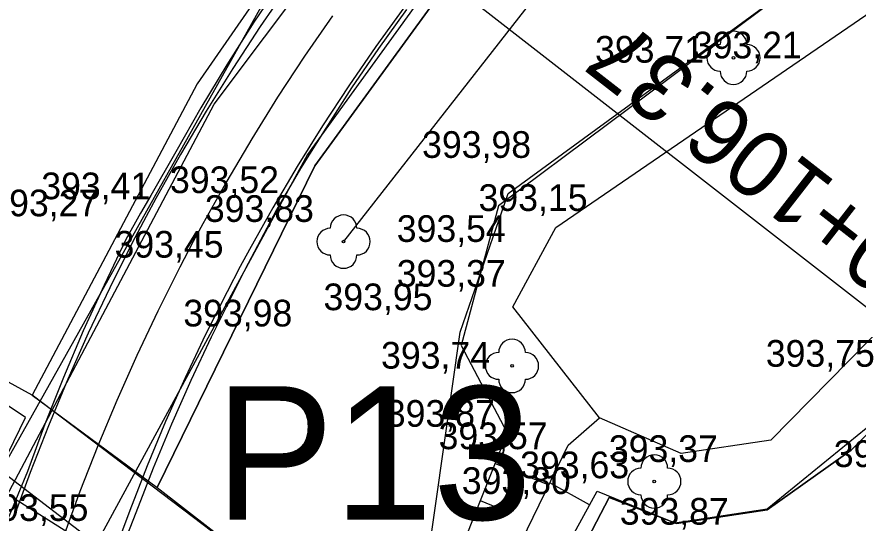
# Model space of a CAD drawing. Extents: x -574342 to -507939, y -1144044 to -1123894.
# Drawn here: x -508540.43 to -508508.86, y -1143172.06 to -1143153.08 of the extents above; entities that cross this region are included whole.
import ezdxf

# ---------------------------------------------------------------- set-up
doc = ezdxf.new("R2010")
doc.units = 0
for name, color, linetype in [('01_PARCELY_NAVRH_PC', 7, 'Continuous'), ('01_PARCELY_NAVRH_VHO', 7, 'Continuous'), ('01_PARCELY_NAVRH_ŽP', 7, 'Continuous'), ('03_PC_OBJEKTY_POP_NAVRH', 7, 'Continuous'), ('05_VHO_V_TOK_STAV', 7, 'Continuous'), ('1000', 7, 'Continuous'), ('18', 7, 'Continuous'), ('21', 7, 'Continuous'), ('23', 7, 'Continuous'), ('37', 7, 'Continuous'), ('42', 7, 'Continuous'), ('51', 7, 'Continuous'), ('54', 7, 'Continuous'), ('55', 7, 'Continuous'), ('60', 7, 'Continuous'), ('61', 7, 'Continuous'), ('Level 255', 7, 'Continuous'), ('Level24', 7, 'Continuous')]:
    doc.layers.add(name, color=color, linetype=linetype)

msp = doc.modelspace()

# ---------------------------------------------------------------- linework, layer by layer
at = {"layer": '01_PARCELY_NAVRH_PC'}
msp.add_lwpolyline([(-508539.86, -1143167.27), (-508535.17, -1143170.73), (-508529.25, -1143158.67), (-508513.07, -1143136.47), (-508505.79, -1143121.37), (-508501.93, -1143102.81), (-508501.63, -1143092.13), (-508497.53, -1143088.05), (-508492.06, -1143088.51), (-508489.36, -1143093.44), (-508498.08, -1143065.7), (-508506.03, -1143042.25), (-508507.09, -1143063.68), (-508507.1, -1143101.54), (-508510.16, -1143116.01), (-508515.95, -1143130.65), (-508519.02, -1143135.54), (-508530.41, -1143150.9), (-508533.66, -1143155.6)], close=True, dxfattribs=at)
msp.add_lwpolyline([(-508539.86, -1143167.27), (-508535.17, -1143170.73), (-508529.25, -1143158.67), (-508513.07, -1143136.47), (-508505.79, -1143121.37), (-508501.93, -1143102.81), (-508501.63, -1143092.13), (-508497.53, -1143088.05), (-508492.06, -1143088.51), (-508489.36, -1143093.44), (-508498.08, -1143065.7), (-508506.03, -1143042.25), (-508507.09, -1143063.68), (-508507.1, -1143101.54), (-508510.16, -1143116.01), (-508515.95, -1143130.65), (-508519.02, -1143135.54), (-508530.41, -1143150.9), (-508533.66, -1143155.6)], close=True, dxfattribs=at)
at = {"layer": '01_PARCELY_NAVRH_VHO'}
for points in [[(-508487.01, -1143113.01), (-508483.82, -1143117.57), (-508479.46, -1143126.74), (-508476.26, -1143134.7), (-508479.68, -1143136.88), (-508479.12, -1143143.52), (-508481.34, -1143149.03), (-508486.83, -1143153.3), (-508497.89, -1143158.09), (-508509.12, -1143169.33), (-508512.27, -1143171.56), (-508515.68, -1143172.08), (-508518.2, -1143171.1), (-508521.06, -1143176.58), (-508513.26, -1143177.6), (-508509.38, -1143179.27), (-508507.52, -1143173.92), (-508499.36, -1143164.43), (-508491.25, -1143159.19), (-508480.5, -1143156.13), (-508471.45, -1143157.79), (-508463.3, -1143163.03)], [(-508461.87, -1143244.49), (-508467.98, -1143243.62), (-508478.66, -1143222.38), (-508487.9, -1143213.8), (-508496.38, -1143198.1), (-508504.26, -1143191.1), (-508516.39, -1143188), (-508530.07, -1143174.68), (-508525.32, -1143175.64), (-508523.79, -1143164.91), (-508521.99, -1143159.7), (-508510.09, -1143151.01), (-508503.75, -1143144.67), (-508499.11, -1143135.6), (-508498.41, -1143129.24), (-508498.01, -1143119.91), (-508496.68, -1143115.27)], [(-508461.81, -1143244.49), (-508467.98, -1143243.62), (-508478.66, -1143222.38), (-508487.9, -1143213.8), (-508496.38, -1143198.1), (-508504.26, -1143191.1), (-508516.39, -1143188), (-508530.07, -1143174.68), (-508539.86, -1143167.27), (-508547.02, -1143163.34), (-508553.27, -1143164.53), (-508559.77, -1143166.35), (-508565.39, -1143163.91), (-508571.39, -1143166.22), (-508578.23, -1143159.53)]]:
    msp.add_lwpolyline(points, dxfattribs=at)
at = {"layer": '01_PARCELY_NAVRH_ŽP'}
for points in [[(-508523.79, -1143164.91), (-508521.99, -1143159.7), (-508510.09, -1143151.01), (-508503.75, -1143144.67), (-508499.11, -1143135.6), (-508498.41, -1143129.24), (-508498.01, -1143119.91), (-508496.68, -1143115.27), (-508492.61, -1143111.73), (-508487.01, -1143113.01), (-508489.36, -1143093.44), (-508492.06, -1143088.51), (-508497.53, -1143088.05), (-508501.63, -1143092.13), (-508501.93, -1143102.81), (-508505.79, -1143121.37), (-508513.07, -1143136.47), (-508529.25, -1143158.67), (-508535.17, -1143170.73), (-508530.07, -1143174.68), (-508525.32, -1143175.64)], [(-508521.06, -1143176.58), (-508518.2, -1143171.1), (-508515.68, -1143172.08), (-508512.27, -1143171.56), (-508509.12, -1143169.33), (-508497.89, -1143158.09), (-508486.83, -1143153.3), (-508481.34, -1143149.03), (-508479.12, -1143143.52), (-508479.68, -1143136.88), (-508476.26, -1143134.7), (-508463.3, -1143163.03), (-508471.45, -1143157.79), (-508480.5, -1143156.13), (-508491.25, -1143159.19), (-508499.36, -1143164.43), (-508507.52, -1143173.92), (-508509.38, -1143179.27), (-508513.26, -1143177.6)]]:
    msp.add_lwpolyline(points, close=True, dxfattribs=at)
msp.add_lwpolyline([(-508584.79, -1143151.71), (-508539.57, -1143146.61), (-508530.41, -1143150.9), (-508533.66, -1143155.6), (-508539.86, -1143167.27), (-508547.02, -1143163.34), (-508553.27, -1143164.53), (-508559.77, -1143166.35), (-508565.39, -1143163.91), (-508571.39, -1143166.22), (-508578.23, -1143159.53)], dxfattribs=at)
at = {"layer": '05_VHO_V_TOK_STAV'}
msp.add_lwpolyline([(-508453.89, -1143245.84), (-508469.84, -1143247.46), (-508476.067, -1143236.175), (-508482.77, -1143224.26), (-508489.11, -1143218.88), (-508496.94, -1143217.04), (-508494.75, -1143210.95), (-508502.24, -1143200.02), (-508504.69, -1143198.72), (-508508.04, -1143199.26), (-508513.72, -1143198.12), (-508516.16, -1143196.14), (-508515.31, -1143194.32), (-508517.287, -1143192.866), (-508519.733, -1143191.098), (-508522.24, -1143189.31), (-508524.27, -1143185.62), (-508530.674, -1143178.031), (-508542.01, -1143169.37), (-508547.92, -1143166.82), (-508560.33, -1143168.91), (-508565.27, -1143165.89), (-508572.15, -1143167.86), (-508577.98, -1143162.03)], dxfattribs=at)
at = {"layer": '1000'}
for points in [[(-508530.477, -1143151.708), (-508531.533, -1143153.28), (-508532.551, -1143154.877), (-508533.529, -1143156.497), (-508534.469, -1143158.14), (-508535.405, -1143159.783), (-508535.797, -1143160.446), (-508536.338, -1143161.431), (-508537.161, -1143163.136), (-508537.942, -1143164.859), (-508538.681, -1143166.6), (-508539.378, -1143168.358), (-508540.035, -1143170.13), (-508540.756, -1143171.879)], [(-508530.225, -1143151.886), (-508531.296, -1143153.44), (-508532.33, -1143155.018), (-508533.328, -1143156.619), (-508534.289, -1143158.243), (-508535.213, -1143159.888), (-508535.577, -1143160.563), (-508536.098, -1143161.555), (-508536.944, -1143163.241), (-508537.752, -1143164.947), (-508538.52, -1143166.67), (-508539.248, -1143168.411), (-508539.936, -1143170.168), (-508540.583, -1143171.94)], [(-508525.906, -1143152.739), (-508526.958, -1143154.193), (-508527.976, -1143155.671), (-508528.96, -1143157.172), (-508529.91, -1143158.695), (-508530.824, -1143160.24), (-508531.702, -1143161.805), (-508532.048, -1143162.447), (-508532.544, -1143163.391), (-508533.349, -1143164.995), (-508534.117, -1143166.617), (-508534.848, -1143168.256), (-508535.54, -1143169.912), (-508536.195, -1143171.583), (-508536.811, -1143173.269)], [(-508525.806, -1143152.813), (-508526.855, -1143154.266), (-508527.871, -1143155.742), (-508528.834, -1143157.253), (-508529.785, -1143158.771), (-508530.692, -1143160.316), (-508531.529, -1143161.9), (-508531.861, -1143162.547), (-508532.342, -1143163.495), (-508533.142, -1143165.095), (-508533.905, -1143166.714), (-508534.63, -1143168.35), (-508535.316, -1143170.003), (-508535.963, -1143171.671), (-508536.612, -1143173.339)]]:
    msp.add_lwpolyline(points, dxfattribs=at)
at = {"layer": '21'}
msp.add_lwpolyline([(-508528.592, -1143153.04), (-508529.636, -1143154.555), (-508530.645, -1143156.095), (-508531.619, -1143157.657), (-508532.556, -1143159.242), (-508533.457, -1143160.847), (-508533.813, -1143161.505), (-508534.321, -1143162.473), (-508535.147, -1143164.118), (-508535.934, -1143165.782), (-508536.684, -1143167.463), (-508537.394, -1143169.161), (-508538.065, -1143170.875), (-508538.697, -1143172.605)], dxfattribs=at)
at = {"layer": '23'}
msp.add_lwpolyline([(-508526.399, -1143150.082), (-508505.084, -1143166.654)], dxfattribs=at)
at = {"layer": '37'}
for points in [[(-508544.44, -1143182.59), (-508541.04, -1143171.49), (-508533.03, -1143156.36), (-508515.99, -1143133.69), (-508511.59, -1143124.92)], [(-508544.44, -1143182.59), (-508541.04, -1143171.49), (-508533.03, -1143156.36), (-508515.99, -1143133.69), (-508511.59, -1143124.92)], [(-508508.39, -1143126.78), (-508512.62, -1143134.91), (-508529.52, -1143158.24), (-508537.33, -1143172.61), (-508540.68, -1143183.59)], [(-508508.39, -1143126.78), (-508512.62, -1143134.91), (-508529.52, -1143158.24), (-508537.33, -1143172.61), (-508540.68, -1143183.59)]]:
    msp.add_lwpolyline(points, dxfattribs=at)
at = {"layer": '42'}
msp.add_lwpolyline([(-508584.52, -1143185.46), (-508576.94, -1143184.13), (-508565.72, -1143180.04), (-508541.6, -1143171.1), (-508528.13, -1143147.12), (-508515.55, -1143126.37), (-508515.49, -1143110.99), (-508517.48, -1143108.63), (-508537.36, -1143120.57)], dxfattribs=at)
msp.add_lwpolyline([(-508584.52, -1143185.46), (-508576.94, -1143184.13), (-508565.72, -1143180.04), (-508541.6, -1143171.1), (-508528.13, -1143147.12), (-508515.55, -1143126.37), (-508515.49, -1143110.99), (-508517.48, -1143108.63), (-508537.36, -1143120.57)], dxfattribs=at)
at = {"layer": '51'}
msp.add_lwpolyline([(-508520.2, -1143160.98), (-508507.66, -1143152.38), (-508503.68, -1143148.5), (-508498.94, -1143141.93), (-508496.26, -1143135.35), (-508495.95, -1143129.08), (-508495.44, -1143120.19), (-508493.12, -1143115.06), (-508490.39, -1143115.19), (-508486.94, -1143118.54), (-508484.73, -1143123.98), (-508484.03, -1143128.35), (-508482.47, -1143135.96), (-508481.24, -1143143.89), (-508483.67, -1143147.96), (-508487.25, -1143151.23), (-508497.6, -1143155.8), (-508504.12, -1143160.81), (-508512.14, -1143168.95), (-508515.5, -1143169.45), (-508518.57, -1143168.12), (-508521.82, -1143163.95)], close=True, dxfattribs=at)
msp.add_lwpolyline([(-508520.2, -1143160.98), (-508507.66, -1143152.38), (-508503.68, -1143148.5), (-508498.94, -1143141.93), (-508496.26, -1143135.35), (-508495.95, -1143129.08), (-508495.44, -1143120.19), (-508493.12, -1143115.06), (-508490.39, -1143115.19), (-508486.94, -1143118.54), (-508484.73, -1143123.98), (-508484.03, -1143128.35), (-508482.47, -1143135.96), (-508481.24, -1143143.89), (-508483.67, -1143147.96), (-508487.25, -1143151.23), (-508497.6, -1143155.8), (-508504.12, -1143160.81), (-508512.14, -1143168.95), (-508515.5, -1143169.45), (-508518.57, -1143168.12), (-508521.82, -1143163.95)], close=True, dxfattribs=at)
at = {"layer": '54'}
for centre in [(-508513.54, -1143154.62), (-508528.17, -1143161.51), (-508521.85, -1143166.17), (-508516.51, -1143170.5)]:
    msp.add_circle(centre, 0.05, dxfattribs=at)
for centre, start, end in [((-508513.54, -1143154.12), 0, 180), ((-508514.04, -1143154.62), 90, 270), ((-508513.04, -1143154.62), 270, 90), ((-508513.54, -1143155.12), 180, 0), ((-508528.17, -1143161.01), 0, 180), ((-508528.67, -1143161.51), 90, 270), ((-508527.67, -1143161.51), 270, 90), ((-508528.17, -1143162.01), 180, 0), ((-508521.85, -1143165.67), 0, 180), ((-508522.35, -1143166.17), 90, 270), ((-508521.35, -1143166.17), 270, 90), ((-508521.85, -1143166.67), 180, 0), ((-508516.51, -1143170), 0, 180), ((-508517.01, -1143170.5), 90, 270), ((-508516.01, -1143170.5), 270, 90), ((-508516.51, -1143171), 180, 0)]:
    msp.add_arc(centre, 0.5, start, end, dxfattribs=at)
at = {"layer": '55'}
msp.add_lwpolyline([(-508498.88, -1143086.48), (-508499.14, -1143104.9), (-508504.08, -1143125.77), (-508509.69, -1143137.89), (-508528.17, -1143161.51)], dxfattribs=at)
msp.add_lwpolyline([(-508498.88, -1143086.48), (-508499.14, -1143104.9), (-508504.08, -1143125.77), (-508509.69, -1143137.89), (-508528.17, -1143161.51)], dxfattribs=at)
at = {"layer": '60'}
for points in [[(-508515.74, -1143172.05), (-508512.28, -1143171.53), (-508508.56, -1143168.5), (-508497.82, -1143157.99), (-508486.77, -1143153.18), (-508481.27, -1143148.82), (-508479.19, -1143143.42), (-508479.72, -1143136.69), (-508476.24, -1143134.48), (-508476.7, -1143133.48), (-508480.34, -1143134.37), (-508481.13, -1143128.49), (-508479.36, -1143127.67), (-508479.81, -1143126.52), (-508482.03, -1143126.91), (-508483.98, -1143117.49), (-508487.17, -1143112.95)], [(-508515.74, -1143172.05), (-508512.28, -1143171.53), (-508508.56, -1143168.5), (-508497.82, -1143157.99), (-508486.77, -1143153.18), (-508481.27, -1143148.82), (-508479.19, -1143143.42), (-508479.72, -1143136.69), (-508476.24, -1143134.48), (-508476.7, -1143133.48), (-508480.34, -1143134.37), (-508481.13, -1143128.49), (-508479.36, -1143127.67), (-508479.81, -1143126.52), (-508482.03, -1143126.91), (-508483.98, -1143117.49), (-508487.17, -1143112.95)], [(-508496.69, -1143115.41), (-508498.11, -1143120.78), (-508498.36, -1143129.97), (-508499.28, -1143136.1), (-508504.42, -1143145.69), (-508510.09, -1143151.01), (-508522.36, -1143160.17), (-508523.76, -1143165.4), (-508522.03, -1143168.68), (-508525.16, -1143176.55)], [(-508496.69, -1143115.41), (-508498.11, -1143120.78), (-508498.36, -1143129.97), (-508499.28, -1143136.1), (-508504.42, -1143145.69), (-508510.09, -1143151.01), (-508522.36, -1143160.17), (-508523.76, -1143165.4), (-508522.03, -1143168.68), (-508525.16, -1143176.55)], [(-508549.33, -1143169.24), (-508544.33, -1143171.35), (-508541.42, -1143170.78), (-508540.11, -1143168.1), (-508541.97, -1143166.87), (-508547.52, -1143164.27)], [(-508549.33, -1143169.24), (-508544.33, -1143171.35), (-508541.42, -1143170.78), (-508540.11, -1143168.1), (-508541.97, -1143166.87), (-508547.52, -1143164.27)], [(-508524.5, -1143179.18), (-508523.67, -1143177.21), (-508519.74, -1143169.14), (-508518.57, -1143168.12)], [(-508524.5, -1143179.18), (-508523.67, -1143177.21), (-508519.74, -1143169.14), (-508518.57, -1143168.12)], [(-508522.02, -1143177), (-508518.66, -1143170.86), (-508515.74, -1143172.05)], [(-508522.02, -1143177), (-508518.66, -1143170.86), (-508515.74, -1143172.05)]]:
    msp.add_lwpolyline(points, dxfattribs=at)
at = {"layer": '61'}
for p, q in [((-508522.485, -1143169.823), (-508520.464, -1143170.627)), ((-508522.485, -1143169.823), (-508520.464, -1143170.627)), ((-508518.94, -1143171.371), (-508520.429, -1143170.556)), ((-508518.94, -1143171.371), (-508520.429, -1143170.556)), ((-508523.039, -1143171.217), (-508522.401, -1143171.471)), ((-508523.039, -1143171.217), (-508522.401, -1143171.471))]:
    msp.add_line(p, q, dxfattribs=at)
at = {"layer": 'Level24'}
msp.add_lwpolyline([(-508541.888, -1143170.288), (-508536.593, -1143173.608)], dxfattribs=at)

# ---------------------------------------------------------------- texts
at = {"layer": '03_PC_OBJEKTY_POP_NAVRH'}
msp.add_text('P13', height=5, dxfattribs=at).set_placement((-508533, -1143171.932))
at = {"layer": '18'}
msp.add_text('TK0+106.37', height=2.5, rotation=142.1355, dxfattribs=at).set_placement((-508503.242, -1143164.286))
at = {"layer": 'Level 255'}
for s, p in [('393,71', (-508518.735, -1143154.8)), ('393,21', (-508515.065, -1143154.64)), ('393,98', (-508525.225, -1143158.37)), ('393,41', (-508539.515, -1143159.92)), ('393,52', (-508534.685, -1143159.69)), ('393,27', (-508541.465, -1143160.56)), ('393,15', (-508523.105, -1143160.36)), ('393,83', (-508533.375, -1143160.77)), ('393,54', (-508526.175, -1143161.52)), ('393,45', (-508536.765, -1143162.11)), ('393,37', (-508526.175, -1143163.2)), ('393,95', (-508528.925, -1143164.08)), ('393,98', (-508534.185, -1143164.69)), ('393,75', (-508512.325, -1143166.2)), ('393,74', (-508526.765, -1143166.27)), ('393,87', (-508526.585, -1143168.45)), ('393,57', (-508524.605, -1143169.29)), ('393,37', (-508518.215, -1143169.77)), ('394,00', (-508509.775, -1143169.96)), ('393,63', (-508521.545, -1143170.38)), ('393,80', (-508523.735, -1143170.97)), ('393,55', (-508541.835, -1143171.98)), ('393,87', (-508517.805, -1143172.12))]:
    msp.add_text(s, height=1, dxfattribs=at).set_placement(p)

doc.saveas('drawing.dxf')
